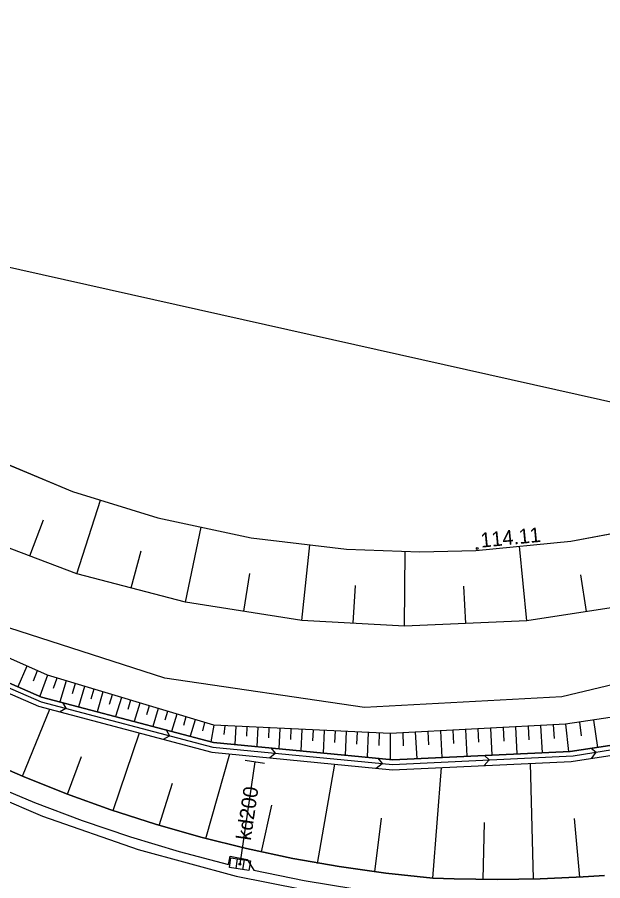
# Model space of a CAD drawing. Extents: x 6424617 to 6425697, y 5665845 to 5667190.
# Drawn here: x 6425370.87 to 6425400.58, y 5667018.77 to 5667062.6 of the extents above; entities that cross this region are included whole.
import ezdxf

# ---------------------------------------------------------------- set-up
doc = ezdxf.new("R2010")
doc.units = 0
for name, color, linetype in [('Warstwa 12', 7, 'Continuous'), ('Warstwa 13', 7, 'Continuous'), ('Warstwa 14', 7, 'Continuous'), ('Warstwa 2', 7, 'Continuous'), ('Warstwa 20', 7, 'Continuous'), ('Warstwa 21', 7, 'Continuous'), ('Warstwa 25', 7, 'Continuous'), ('Warstwa 4', 7, 'Continuous'), ('Warstwa 6', 7, 'Continuous'), ('Warstwa 63', 7, 'Continuous'), ('Warstwa 8', 7, 'Continuous'), ('Warstwa 9', 7, 'Continuous')]:
    doc.layers.add(name, color=color, linetype=linetype)

msp = doc.modelspace()

# ---------------------------------------------------------------- linework, layer by layer
at = {"layer": 'Warstwa 12'}
msp.add_lwpolyline([(6425382.93, 5667024.8), (6425382.17, 5667019.61)], dxfattribs=at)
at = {"layer": 'Warstwa 14'}
msp.add_circle((6425382.17, 5667019.61), 0.045, dxfattribs=at)
at = {"layer": 'Warstwa 2'}
msp.add_lwpolyline([(6425415.848, 5667022.904), (6425413.014, 5667031.578), (6425398.506, 5667028.098), (6425388.493, 5667027.569), (6425378.357, 5667029.052), (6425368.849, 5667032.115), (6425360.306, 5667036.541), (6425352.393, 5667042.606), (6425345.686, 5667050.059), (6425341.602, 5667056.373)], dxfattribs=at)
at = {"layer": 'Warstwa 20'}
for points in [[(6425426.154, 5667037.416), (6425425.11, 5667036.57), (6425416.37, 5667031.8), (6425412.82, 5667030.22), (6425405.73, 5667027.76), (6425398.7, 5667026.71), (6425389.8, 5667026.25), (6425380.84, 5667026.66), (6425372.41, 5667029.2), (6425363.01, 5667033.38), (6425354.67, 5667039.07), (6425347.24, 5667046.39), (6425340.78, 5667055.29), (6425340.154, 5667056.698)], [(6425419.317, 5667038.949), (6425418.431, 5667038.419), (6425414.322, 5667036.436), (6425408.231, 5667034.315), (6425402.777, 5667032.893), (6425396.729, 5667031.966), (6425390.529, 5667031.694), (6425385.317, 5667031.988), (6425379.417, 5667032.906), (6425373.901, 5667034.355), (6425369.112, 5667036.157), (6425364.576, 5667038.412), (6425360.101, 5667041.246), (6425355.111, 5667045.291), (6425352.009, 5667048.415), (6425350.027, 5667050.731), (6425347.939, 5667053.52), (6425346.768, 5667055.215)], [(6425368.748, 5667025.117), (6425371.145, 5667024.081), (6425373.364, 5667023.189), (6425375.614, 5667022.373), (6425377.89, 5667021.636), (6425380.191, 5667020.979), (6425382.512, 5667020.401), (6425384.853, 5667019.904), (6425387.209, 5667019.489), (6425389.578, 5667019.156), (6425391.958, 5667018.904), (6425393.048, 5667018.865), (6425394.138, 5667018.843), (6425395.229, 5667018.836), (6425396.319, 5667018.844), (6425397.41, 5667018.869), (6425398.5, 5667018.91), (6425399.589, 5667018.967), (6425400.677, 5667019.039)]]:
    msp.add_lwpolyline(points, dxfattribs=at)
at = {"layer": 'Warstwa 21'}
msp.add_line((6425383.425, 5667024.728), (6425382.435, 5667024.872), dxfattribs=at)
for points in [[(6425338.07, 5667057.165), (6425339.34, 5667054.315), (6425345.877, 5667045.114), (6425353.516, 5667037.754), (6425362.341, 5667031.802), (6425371.949, 5667027.628), (6425380.75, 5667025.298), (6425389.917, 5667024.402), (6425398.977, 5667024.829), (6425400.846, 5667025.116), (6425406.21, 5667025.939), (6425417.18, 5667030.172), (6425426.161, 5667035.051), (6425428.488, 5667036.893)], [(6425427.865, 5667037.033), (6425425.888, 5667035.466), (6425416.958, 5667030.616), (6425406.078, 5667026.421), (6425398.926, 5667025.33), (6425389.926, 5667024.912), (6425380.839, 5667025.787), (6425372.108, 5667028.095), (6425362.59, 5667032.248), (6425353.833, 5667038.148), (6425346.252, 5667045.437), (6425339.775, 5667054.567), (6425338.677, 5667057.029)], [(6425352.834, 5667053.855), (6425353.989, 5667052.483), (6425356.784, 5667049.517), (6425361.844, 5667045.084), (6425366.702, 5667041.707), (6425368.146, 5667040.841), (6425373.672, 5667038.521), (6425378.007, 5667037.188), (6425382.736, 5667036.181), (6425387.572, 5667035.607), (6425391.3, 5667035.468), (6425394.149, 5667035.539), (6425398.969, 5667036.01), (6425403.383, 5667036.839), (6425406.688, 5667037.718), (6425408.423, 5667038.273), (6425411.716, 5667039.504), (6425413.349, 5667040.287)]]:
    msp.add_lwpolyline(points, dxfattribs=at)
at = {"layer": 'Warstwa 25'}
msp.add_circle((6425394.217, 5667035.632), 0.045, dxfattribs=at)
at = {"layer": 'Warstwa 4'}
for p, q in [((6425382.032, 5667019.882), (6425381.961, 5667019.387)), ((6425382.379, 5667019.833), (6425382.308, 5667019.338))]:
    msp.add_line(p, q, dxfattribs=at)
msp.add_lwpolyline([(6425381.711, 5667019.929), (6425382.7, 5667019.786), (6425382.629, 5667019.291), (6425381.64, 5667019.434)], close=True, dxfattribs=at)
at = {"layer": 'Warstwa 6'}
msp.add_lwpolyline([(6425369.363, 5667023.748), (6425371.748, 5667022.746), (6425374.167, 5667021.83), (6425376.616, 5667020.999), (6425379.094, 5667020.256), (6425381.597, 5667019.601), (6425381.675, 5667020.01), (6425382.532, 5667019.844), (6425382.873, 5667019.308), (6425385.433, 5667018.786), (6425388.01, 5667018.357)], dxfattribs=at)
at = {"layer": 'Warstwa 63'}
msp.add_lwpolyline([(6425341.164, 5665895.978), (6425588.9, 5667000.928), (6424898.307, 5667155.763), (6424650.57, 5666050.814)], close=True, dxfattribs=at)
at = {"layer": 'Warstwa 8'}
for p, q in [((6425368.146, 5667040.841), (6425373.672, 5667038.521)), ((6425373.672, 5667038.521), (6425378.007, 5667037.188)), ((6425378.007, 5667037.188), (6425382.736, 5667036.181)), ((6425398.969, 5667036.01), (6425403.383, 5667036.839)), ((6425382.736, 5667036.181), (6425387.572, 5667035.607)), ((6425394.149, 5667035.539), (6425398.969, 5667036.01)), ((6425387.572, 5667035.607), (6425391.3, 5667035.468)), ((6425391.3, 5667035.468), (6425394.149, 5667035.539)), ((6425367.427, 5667024.085), (6425372.155, 5667022.05)), ((6425372.155, 5667022.05), (6425377.014, 5667020.353)), ((6425377.014, 5667020.353), (6425381.981, 5667019.003)), ((6425381.981, 5667019.003), (6425387.03, 5667018.005))]:
    msp.add_line(p, q, dxfattribs=at)
at = {"layer": 'Warstwa 9'}
for p, q in [((6425373.901, 5667034.355), (6425375.09, 5667038.085)), ((6425371.506, 5667035.256), (6425372.198, 5667037.093)), ((6425379.417, 5667032.906), (6425380.211, 5667036.719)), ((6425385.317, 5667031.988), (6425385.722, 5667035.827)), ((6425396.729, 5667031.966), (6425396.357, 5667035.755)), ((6425376.659, 5667033.63), (6425377.155, 5667035.516)), ((6425390.529, 5667031.694), (6425390.552, 5667035.496)), ((6425382.367, 5667032.447), (6425382.667, 5667034.36)), ((6425399.753, 5667032.43), (6425399.47, 5667034.299)), ((6425387.923, 5667031.841), (6425388.03, 5667033.751)), ((6425393.629, 5667031.83), (6425393.542, 5667033.728)), ((6425362.498, 5667031.967), (6425372.093, 5667027.852)), ((6425371.366, 5667029.664), (6425370.902, 5667028.621)), ((6425371.888, 5667029.432), (6425371.673, 5667028.905)), ((6425372.41, 5667029.2), (6425372.014, 5667028.136)), ((6425372.878, 5667029.059), (6425372.7, 5667028.526)), ((6425373.347, 5667028.918), (6425373.027, 5667027.852)), ((6425373.815, 5667028.777), (6425373.657, 5667028.252)), ((6425374.283, 5667028.636), (6425373.972, 5667027.602)), ((6425374.751, 5667028.494), (6425374.598, 5667027.986)), ((6425375.22, 5667028.353), (6425374.919, 5667027.352)), ((6425372.093, 5667027.852), (6425380.803, 5667025.545)), ((6425373.16, 5667027.817), (6425373.33, 5667027.525)), ((6425375.688, 5667028.212), (6425375.54, 5667027.72)), ((6425376.157, 5667028.071), (6425375.866, 5667027.102)), ((6425376.625, 5667027.93), (6425376.482, 5667027.454)), ((6425371.145, 5667024.081), (6425372.524, 5667027.476)), ((6425373.02, 5667027.345), (6425373.33, 5667027.525)), ((6425377.093, 5667027.789), (6425376.811, 5667026.852)), ((6425377.562, 5667027.648), (6425377.423, 5667027.188)), ((6425378.03, 5667027.507), (6425377.758, 5667026.602)), ((6425378.499, 5667027.365), (6425378.365, 5667026.921)), ((6425378.967, 5667027.224), (6425378.705, 5667026.352)), ((6425379.435, 5667027.083), (6425379.306, 5667026.655)), ((6425379.903, 5667026.942), (6425379.65, 5667026.102)), ((6425400.106, 5667026.92), (6425400.313, 5667025.541)), ((6425380.372, 5667026.801), (6425380.272, 5667026.382)), ((6425380.84, 5667026.66), (6425380.697, 5667025.825)), ((6425381.4, 5667026.635), (6425381.354, 5667026.194)), ((6425381.96, 5667026.609), (6425381.918, 5667025.683)), ((6425382.52, 5667026.584), (6425382.498, 5667026.106)), ((6425383.08, 5667026.558), (6425383.035, 5667025.576)), ((6425383.64, 5667026.532), (6425383.617, 5667026.027)), ((6425384.2, 5667026.506), (6425384.153, 5667025.468)), ((6425384.76, 5667026.48), (6425384.736, 5667025.947)), ((6425394.25, 5667026.48), (6425394.286, 5667025.798)), ((6425394.886, 5667026.513), (6425394.958, 5667025.146)), ((6425395.522, 5667026.546), (6425395.558, 5667025.861)), ((6425396.157, 5667026.579), (6425396.229, 5667025.205)), ((6425396.793, 5667026.612), (6425396.829, 5667025.923)), ((6425397.429, 5667026.644), (6425397.501, 5667025.264)), ((6425398.064, 5667026.677), (6425398.117, 5667025.986)), ((6425398.7, 5667026.71), (6425398.839, 5667025.326)), ((6425399.403, 5667026.815), (6425399.489, 5667026.124)), ((6425375.737, 5667022.331), (6425377.079, 5667026.27)), ((6425378.289, 5667025.949), (6425378.599, 5667026.129)), ((6425378.427, 5667026.425), (6425378.599, 5667026.129)), ((6425385.32, 5667026.455), (6425385.27, 5667025.36)), ((6425385.88, 5667026.43), (6425385.854, 5667025.868)), ((6425386.44, 5667026.404), (6425386.388, 5667025.253)), ((6425387, 5667026.378), (6425386.973, 5667025.788)), ((6425387.56, 5667026.352), (6425387.505, 5667025.145)), ((6425388.12, 5667026.326), (6425388.092, 5667025.709)), ((6425388.68, 5667026.301), (6425388.623, 5667025.038)), ((6425389.24, 5667026.276), (6425389.227, 5667025.628)), ((6425389.8, 5667026.25), (6425389.804, 5667024.924)), ((6425390.436, 5667026.283), (6425390.454, 5667025.614)), ((6425391.071, 5667026.316), (6425391.142, 5667024.968)), ((6425391.707, 5667026.348), (6425391.742, 5667025.673)), ((6425392.343, 5667026.381), (6425392.414, 5667025.028)), ((6425392.978, 5667026.414), (6425393.014, 5667025.736)), ((6425393.614, 5667026.447), (6425393.685, 5667025.087)), ((6425399.075, 5667025.117), (6425406.143, 5667026.221)), ((6425380.441, 5667020.912), (6425381.654, 5667025.21)), ((6425380.803, 5667025.545), (6425389.91, 5667024.672)), ((6425383.678, 5667025.012), (6425383.959, 5667025.243)), ((6425383.74, 5667025.508), (6425383.959, 5667025.243)), ((6425399.995, 5667025.493), (6425400.257, 5667025.302)), ((6425400.03, 5667024.991), (6425400.257, 5667025.302)), ((6425373.424, 5667023.166), (6425374.135, 5667025.081)), ((6425389.093, 5667024.483), (6425389.384, 5667024.723)), ((6425389.168, 5667024.985), (6425389.384, 5667024.723)), ((6425389.91, 5667024.672), (6425399.075, 5667025.117)), ((6425394.563, 5667024.621), (6425394.826, 5667024.911)), ((6425394.586, 5667025.128), (6425394.826, 5667024.911)), ((6425397.065, 5667018.86), (6425396.919, 5667024.732)), ((6425386.1, 5667019.643), (6425386.98, 5667024.689)), ((6425391.958, 5667018.904), (6425392.397, 5667024.519)), ((6425378.078, 5667021.579), (6425378.742, 5667023.722)), ((6425383.259, 5667020.23), (6425383.794, 5667022.614)), ((6425389.023, 5667019.226), (6425389.359, 5667021.939)), ((6425394.513, 5667018.838), (6425394.586, 5667021.727)), ((6425399.415, 5667018.956), (6425399.15, 5667021.932))]:
    msp.add_line(p, q, dxfattribs=at)
for points in [[(6425338.07, 5667057.165), (6425339.34, 5667054.315), (6425345.877, 5667045.114), (6425353.516, 5667037.754), (6425362.341, 5667031.802), (6425371.949, 5667027.628), (6425380.75, 5667025.298), (6425389.917, 5667024.402), (6425398.977, 5667024.829), (6425400.846, 5667025.116), (6425406.21, 5667025.939), (6425417.18, 5667030.172), (6425426.161, 5667035.051), (6425428.488, 5667036.893)], [(6425338.07, 5667057.165), (6425339.34, 5667054.315), (6425345.877, 5667045.114), (6425353.516, 5667037.754), (6425362.341, 5667031.802), (6425371.949, 5667027.628), (6425380.75, 5667025.298), (6425389.917, 5667024.402), (6425398.977, 5667024.829), (6425400.846, 5667025.116), (6425406.21, 5667025.939), (6425417.18, 5667030.172), (6425426.161, 5667035.051), (6425428.488, 5667036.893)], [(6425427.865, 5667037.033), (6425425.888, 5667035.466), (6425416.958, 5667030.616), (6425406.078, 5667026.421), (6425398.926, 5667025.33), (6425389.926, 5667024.912), (6425380.839, 5667025.787), (6425372.108, 5667028.095), (6425362.59, 5667032.248), (6425353.833, 5667038.148), (6425346.252, 5667045.437), (6425339.775, 5667054.567), (6425338.677, 5667057.029)], [(6425338.677, 5667057.029), (6425339.775, 5667054.567), (6425346.252, 5667045.437), (6425353.833, 5667038.148), (6425362.59, 5667032.248), (6425372.108, 5667028.095), (6425380.839, 5667025.787), (6425389.926, 5667024.912), (6425398.926, 5667025.33), (6425406.078, 5667026.421), (6425416.958, 5667030.616), (6425425.888, 5667035.466), (6425427.865, 5667037.033)], [(6425426.154, 5667037.416), (6425425.11, 5667036.57), (6425416.37, 5667031.8), (6425412.82, 5667030.22), (6425405.73, 5667027.76), (6425398.7, 5667026.71), (6425389.8, 5667026.25), (6425380.84, 5667026.66), (6425372.41, 5667029.2), (6425363.01, 5667033.38), (6425354.67, 5667039.07), (6425347.24, 5667046.39), (6425340.78, 5667055.29), (6425340.154, 5667056.698)], [(6425419.317, 5667038.949), (6425418.431, 5667038.419), (6425414.322, 5667036.436), (6425408.231, 5667034.315), (6425402.777, 5667032.893), (6425396.729, 5667031.966), (6425390.529, 5667031.694), (6425385.317, 5667031.988), (6425379.417, 5667032.906), (6425373.901, 5667034.355), (6425369.112, 5667036.157), (6425364.576, 5667038.412), (6425360.101, 5667041.246), (6425355.111, 5667045.291), (6425352.009, 5667048.415), (6425350.027, 5667050.731), (6425347.939, 5667053.52), (6425346.768, 5667055.215)], [(6425352.834, 5667053.855), (6425353.989, 5667052.483), (6425356.784, 5667049.517), (6425361.844, 5667045.084), (6425366.702, 5667041.707), (6425368.146, 5667040.841), (6425373.672, 5667038.521), (6425378.007, 5667037.188), (6425382.736, 5667036.181), (6425387.572, 5667035.607), (6425391.3, 5667035.468), (6425394.149, 5667035.539), (6425398.969, 5667036.01), (6425403.383, 5667036.839), (6425406.688, 5667037.718), (6425408.423, 5667038.273), (6425411.716, 5667039.504), (6425413.349, 5667040.287)], [(6425400.677, 5667019.039), (6425399.589, 5667018.967), (6425398.5, 5667018.91), (6425397.41, 5667018.869), (6425396.319, 5667018.844), (6425395.229, 5667018.836), (6425394.138, 5667018.843), (6425393.048, 5667018.865), (6425391.958, 5667018.904), (6425389.578, 5667019.156), (6425387.209, 5667019.489), (6425384.853, 5667019.904), (6425382.512, 5667020.401), (6425380.191, 5667020.979), (6425377.89, 5667021.636), (6425375.614, 5667022.373), (6425373.364, 5667023.189), (6425371.145, 5667024.081), (6425368.748, 5667025.117)]]:
    msp.add_lwpolyline(points, dxfattribs=at)

# ---------------------------------------------------------------- texts
at = {"layer": 'Warstwa 13'}
msp.add_text('kd200', height=0.75, rotation=81.6694, dxfattribs=at).set_placement((6425382.722, 5667020.787))
at = {"layer": 'Warstwa 25'}
msp.add_text('114.11', height=0.75, rotation=5.5806, dxfattribs=at).set_placement((6425394.414, 5667035.676))

doc.saveas('drawing.dxf')
